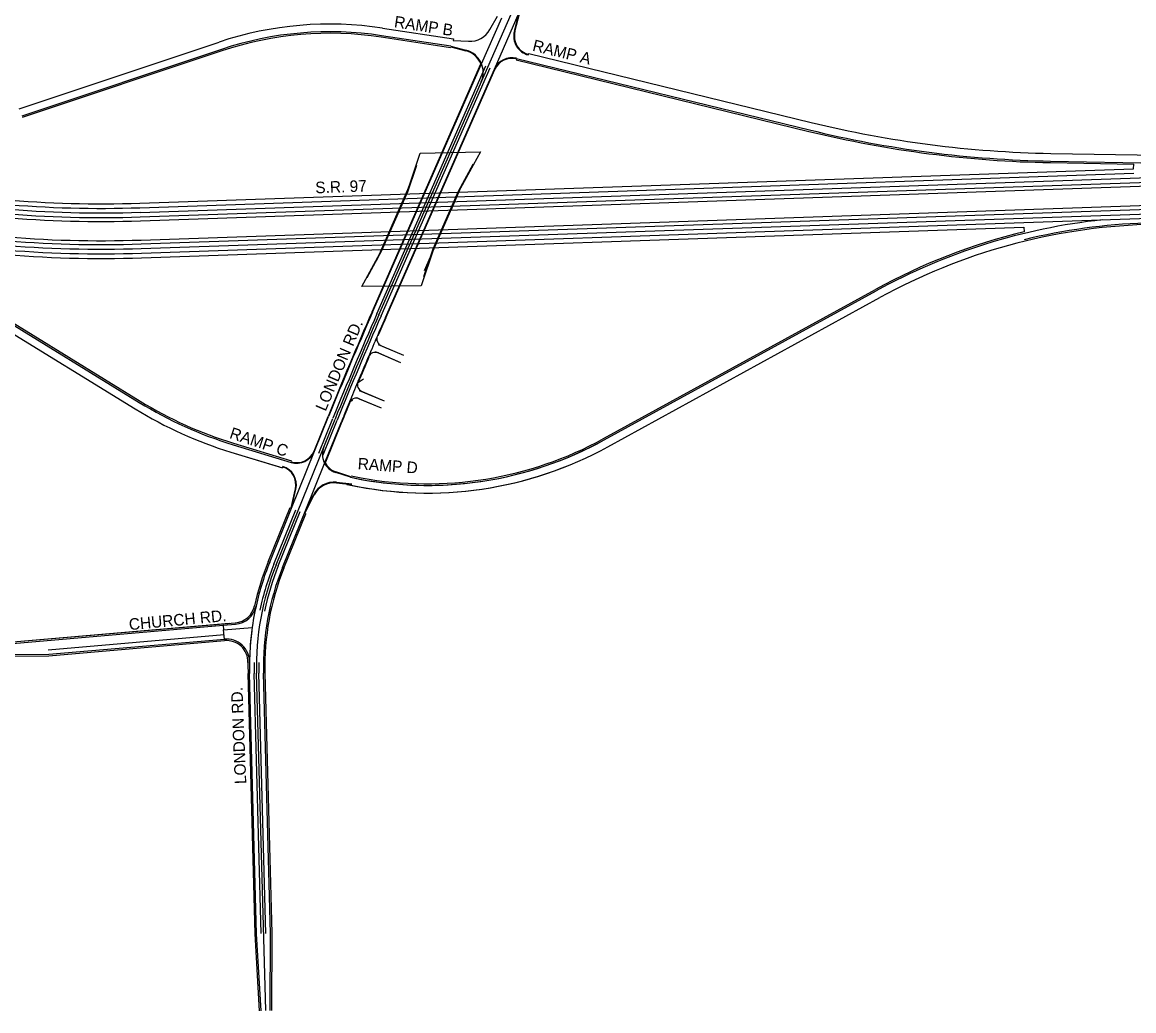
# Model space of a CAD drawing. Extents: x 2315515 to 2326910, y 758186 to 762794.
# Drawn here: x 2319970 to 2322857, y 758186 to 760752 of the extents above; entities that cross this region are included whole.
import ezdxf

# ---------------------------------------------------------------- set-up
doc = ezdxf.new("R2010")
doc.units = 0
for name, color, linetype in [('_CIVIL_CONSTRUCTION', 7, 'Continuous'), ('Bridge_Abutment', 7, 'Continuous'), ('Bridge_Bearing', 7, 'Continuous'), ('Bridge_Deck', 7, 'Continuous'), ('Clipping_Shape', 7, 'Continuous'), ('Default', 7, 'Continuous'), ('Draft_Corr_Final', 7, 'Continuous'), ('Draft_Corr_Range_Final', 7, 'Continuous'), ('Pavement Marking Yellow', 7, 'Continuous'), ('Road_Curb_Face', 7, 'Continuous'), ('TL_Base Extension Sub', 7, 'Continuous'), ('TL_End Condition Cut Tie', 7, 'Continuous'), ('TL_End Condition Ditch Out', 7, 'Continuous'), ('TL_End Condition Hinge', 7, 'Continuous'), ('TL_Pavement Centerline', 7, 'Continuous'), ('TL_Pavement Centerline Sub', 7, 'Continuous')]:
    doc.layers.add(name, color=color, linetype=linetype)

msp = doc.modelspace()

# ---------------------------------------------------------------- linework, layer by layer
at = {"layer": '_CIVIL_CONSTRUCTION'}
for p, q in [((2320276.8, 760236.3), (2324006.3, 760365.3)), ((2320278.5, 760186.3), (2324008.1, 760315.3))]:
    msp.add_line(p, q, dxfattribs=at)
for radius in [2941, 2991]:
    msp.add_arc((2320175.2, 763175.6), radius, 264.9144, 271.9805, dxfattribs=at)
at = {"layer": 'Bridge_Abutment'}
for p, q in [((2320970, 760308.5), (2320994, 760379.5)), ((2321103.2, 760313.3), (2321141.6, 760383.5)), ((2320904.4, 760159.2), (2320970, 760308.5)), ((2321037.2, 760163.2), (2321103.2, 760313.3)), ((2320866, 760089.1), (2320904.4, 760159.2)), ((2321013.2, 760092.1), (2321037.2, 760163.2))]:
    msp.add_line(p, q, dxfattribs=at)
at = {"layer": 'Bridge_Bearing'}
for p, q in [((2320994, 760379.5), (2320970, 760308.5)), ((2321141.6, 760383.5), (2321103.2, 760313.3)), ((2320904.4, 760159.2), (2320970, 760308.5)), ((2321037.2, 760163.2), (2321103.2, 760313.3)), ((2320866, 760089.1), (2320904.4, 760159.2)), ((2321013.2, 760092.1), (2321037.2, 760163.2))]:
    msp.add_line(p, q, dxfattribs=at)
at = {"layer": 'Bridge_Deck'}
for p, q in [((2320891.3, 760134.3), (2320977.7, 760331.1)), ((2320946.3, 760259.5), (2320966.8, 760306.2)), ((2321014.9, 760107.4), (2321107.7, 760318.6)), ((2321083.8, 760264.2), (2321104.3, 760311)), ((2320903.4, 760161.9), (2320924, 760208.7)), ((2321041, 760166.7), (2321061.5, 760213.4))]:
    msp.add_line(p, q, dxfattribs=at)
at = {"layer": 'Clipping_Shape'}
for p, q in [((2320969.1, 760308.8), (2320993.1, 760379.8)), ((2320903.6, 760159.7), (2320969.1, 760308.8)), ((2320865.1, 760089.5), (2320903.6, 760159.7))]:
    msp.add_line(p, q, dxfattribs=at)
msp.add_lwpolyline([(2320852.2, 760066.2), (2320904.3, 760161.4), (2320968.5, 760307.7), (2321003.8, 760411.9), (2321160.3, 760415.2), (2321103.4, 760311.5), (2321039.2, 760165.2), (2321006.2, 760067.6)], close=True, dxfattribs=at)
at = {"layer": 'Default'}
for p, q in [((2320896.6, 759992.2), (2321353.4, 761032.3)), ((2320896.6, 759992.2), (2321353.4, 761032.3)), ((2320896.6, 759992.2), (2321353.4, 761032.3)), ((2320840.7, 759815.8), (2320856, 759826.5)), ((2320820.4, 759766.7), (2320828.3, 759770.7)), ((2320629.4, 759343.1), (2320782.4, 759721.3)), ((2320629.4, 759343.1), (2320782.4, 759721.3)), ((2320629.4, 759343.1), (2320782.4, 759721.3)), ((2320602.3, 758186.1), (2320578.6, 759061.6)), ((2320602.3, 758186.1), (2320578.6, 759061.6)), ((2320602.3, 758186.1), (2320578.6, 759061.6))]:
    msp.add_line(p, q, dxfattribs=at)
for centre, radius, start, end in [((2330052.7, 755971.5), 10000, 156.2923, 157.9768), ((2330052.7, 755971.5), 10000, 156.2923, 157.9768), ((2330052.7, 755971.5), 10000, 156.2923, 157.9768), ((2321278.3, 759080.6), 700, 157.9768, 181.5499), ((2321278.3, 759080.6), 700, 157.9768, 181.5499), ((2321278.3, 759080.6), 700, 157.9768, 181.5499)]:
    msp.add_arc(centre, radius, start, end, dxfattribs=at)
at = {"layer": 'Draft_Corr_Final'}
for p, q in [((2321184.8, 760732.9), (2321204.5, 760767.9)), ((2321248.3, 760728.3), (2321261, 760777.3)), ((2321083.3, 760689.3), (2320902.9, 760716.9)), ((2321089.2, 760704.6), (2321129.4, 760702.5)), ((2320487.5, 760681.4), (2319968.8, 760508)), ((2321083.3, 760689.3), (2321122.2, 760679.3)), ((2321083.3, 760689.3), (2321122.2, 760679.3)), ((2320880.1, 759999.4), (2321163, 760643.5)), ((2320880.1, 759999.4), (2321163, 760643.5)), ((2321253.9, 760658.1), (2322014.4, 760472.4)), ((2321253.9, 760658.1), (2322014.4, 760472.4)), ((2320913.1, 759984.9), (2321196.2, 760629.7)), ((2320913.1, 759984.9), (2321196.2, 760629.7)), ((2322641, 760391.4), (2323391.1, 760378)), ((2322641, 760391.4), (2323391.1, 760378)), ((2321481.7, 759667.3), (2322187.7, 760054.5)), ((2321481.7, 759667.3), (2322187.7, 760054.5)), ((2319848.5, 760026.7), (2320274.1, 759765)), ((2320886.3, 759897), (2320952.1, 759868.7)), ((2320894.2, 759915.3), (2320960, 759887.1)), ((2320895.2, 759893.2), (2320952.1, 759868.7)), ((2320903, 759911.6), (2320960, 759887.1)), ((2320837.1, 759777.7), (2320902.4, 759750.7)), ((2320844.8, 759796.2), (2320910.1, 759769.1)), ((2320845.2, 759774.4), (2320902.4, 759750.7)), ((2320852.8, 759792.8), (2320910.1, 759769.1)), ((2320729.3, 759638), (2320765.7, 759728)), ((2320729.3, 759638), (2320765.7, 759728)), ((2320757.1, 759610.8), (2320799.1, 759714.5)), ((2320757.1, 759610.8), (2320799.1, 759714.5)), ((2320517.6, 759655.1), (2320668.3, 759608.9)), ((2320822.6, 759570.6), (2320784.3, 759582.8)), ((2320822.6, 759570.6), (2320784.3, 759582.8)), ((2320786.3, 759557.6), (2320826.3, 759553.5)), ((2320612.7, 759349.8), (2320680.2, 759516.6)), ((2320669.6, 759490.4), (2320680.9, 759539.8)), ((2320708.3, 759490.2), (2320727.1, 759525.8)), ((2320612.7, 759349.8), (2320669.6, 759490.4)), ((2320646.1, 759336.3), (2320712.8, 759501.1)), ((2320646.1, 759336.3), (2320708.3, 759490.2)), ((2319886.9, 759134), (2320492.1, 759186.2)), ((2320492.1, 759186.2), (2320523.9, 759189)), ((2320492.1, 759186.2), (2320523.9, 759189)), ((2320492.1, 759186.2), (2320493.2, 759174.3)), ((2320495.2, 759150.3), (2320493.2, 759174.3)), ((2320038.8, 759111), (2320495.2, 759150.3)), ((2320038.8, 759111), (2320495.2, 759150.3)), ((2319889, 759110.1), (2320038.8, 759111)), ((2320578.9, 758385.5), (2320560.6, 759061.2)), ((2320578.9, 758385.5), (2320560.6, 759061.2)), ((2320614.8, 758386.5), (2320596.6, 759062.1)), ((2320614.8, 758386.5), (2320596.6, 759062.1)), ((2320614.3, 758186.4), (2320614.8, 758386.5)), ((2320590.3, 758185.7), (2320578.9, 758385.5))]:
    msp.add_line(p, q, dxfattribs=at)
for centre, radius, start, end in [((2320768.6, 759840.1), 887, 81.2923, 108.4803), ((2321132.5, 760762.4), 60, 267.0029, 330.5817), ((2321296.6, 760715.6), 50, 165.3826, 256.2777), ((2321107.3, 760621.2), 60, 336.2923, 75.5817), ((2321107.3, 760621.2), 60, 21.8653, 75.5817), ((2321242, 760609.6), 50, 76.2777, 156.2923), ((2322691.8, 763246.9), 2856, 256.2777, 268.9805), ((2322691.8, 763246.9), 2856, 256.2777, 268.9805), ((2322940.8, 758681.5), 1566, 96.0766, 118.7415), ((2322940.8, 758681.5), 1566, 96.0766, 118.7415), ((2322940.8, 758681.5), 1550, 91.9805, 103.7445), ((2322940.8, 758681.5), 1550, 91.9805, 103.7445), ((2330052.7, 755971.5), 10018, 156.2923, 157.9768), ((2330052.7, 755971.5), 10018, 156.2923, 157.9768), ((2330052.7, 755971.5), 9982, 156.2923, 156.67031), ((2330052.7, 755971.5), 9982, 156.2923, 156.58701), ((2320910.9, 759929.9), 20, 156.587, 246.7596), ((2330052.7, 755971.5), 9982, 156.82209, 157.38068), ((2320887.3, 759874.8), 20, 66.7596, 156.9321), ((2330052.7, 755971.5), 9982, 156.93209, 157.32833), ((2320860.5, 759811.3), 20, 157.3283, 247.5009), ((2330052.7, 755971.5), 9982, 157.60715, 157.9768), ((2320837.5, 759755.9), 20, 67.5009, 157.6734), ((2320826.1, 760662.9), 1054, 238.4184, 252.9768), ((2330052.7, 755971.5), 9982, 157.67342, 157.9768), ((2321022, 760505.5), 956, 257.9603, 298.7415), ((2321022, 760505.5), 956, 258.6432, 298.7415), ((2320682.9, 759656.8), 50, 252.9768, 337.9768), ((2320799.6, 759630.4), 50, 157.9768, 252.2497), ((2320632.2, 759551), 50, 347.0671, 72.9768), ((2320799.6, 759630.4), 50, 200.9838, 252.2497), ((2320780.2, 759497.9), 60, 84.0948, 152.2662), ((2321278.3, 759080.6), 718, 157.9768, 168.1459), ((2321278.3, 759080.6), 718, 157.9768, 168.1459), ((2321278.3, 759080.6), 682, 157.9768, 181.5499), ((2321278.3, 759080.6), 682, 157.9768, 181.5499), ((2320518.7, 759248.7), 60, 274.9294, 347.5179), ((2320518.7, 759248.7), 60, 274.9294, 347.5179), ((2321278.3, 759080.6), 718, 172.8394, 181.5499), ((2320500.4, 759090.6), 60, 359.264, 94.9294), ((2321278.3, 759080.6), 718, 179.264, 181.5499)]:
    msp.add_arc(centre, radius, start, end, dxfattribs=at)
at = {"layer": 'Draft_Corr_Range_Final'}
for p, q in [((2320276.5, 760246.3), (2324006, 760375.3)), ((2320278.9, 760176.4), (2324008.4, 760305.3))]:
    msp.add_line(p, q, dxfattribs=at)
for radius in [2931, 3001]:
    msp.add_arc((2320175.2, 763175.6), radius, 264.9144, 271.9805, dxfattribs=at)
at = {"layer": 'Pavement Marking Yellow'}
for p, q in [((2320891.1, 759994.6), (2321174, 760638.7)), ((2320902.1, 759989.8), (2321185, 760633.9)), ((2320740.4, 759633.5), (2320776.8, 759723.5)), ((2320751.5, 759628.9), (2320787.9, 759719)), ((2320623.8, 759345.3), (2320680.7, 759485.9)), ((2320635, 759340.8), (2320691.8, 759481.4)), ((2320590.9, 758385.8), (2320572.6, 759061.5)), ((2320602.9, 758386.2), (2320584.6, 759061.8))]:
    msp.add_line(p, q, dxfattribs=at)
for centre, radius, start, end in [((2330052.7, 755971.5), 10006, 156.2923, 157.9768), ((2330052.7, 755971.5), 9994, 156.2923, 157.9768), ((2321278.3, 759080.6), 706, 157.9768, 168.1459), ((2321278.3, 759080.6), 694, 157.9768, 168.1459), ((2321278.3, 759080.6), 706, 179.264, 181.5499), ((2321278.3, 759080.6), 694, 179.264, 181.5499)]:
    msp.add_arc(centre, radius, start, end, dxfattribs=at)
at = {"layer": 'Road_Curb_Face'}
for p, q in [((2321249.7, 760727.9), (2321262.5, 760776.9)), ((2321249.7, 760727.9), (2321262.5, 760776.8)), ((2321082.9, 760687.8), (2321121.9, 760677.8)), ((2321083.1, 760687.8), (2321121.9, 760677.8)), ((2320878.8, 760000), (2321161.6, 760644.1)), ((2320878.8, 760000), (2321161.4, 760643.5)), ((2320914.5, 759984.3), (2321197.6, 760629.1)), ((2320727.9, 759638.6), (2320764.3, 759728.6)), ((2320727.9, 759638.6), (2320764.3, 759728.6)), ((2320757.2, 759606.9), (2320800.5, 759714)), ((2320758.5, 759610.3), (2320800.5, 759714)), ((2320823.1, 759572), (2320784.8, 759584.3)), ((2320823.1, 759572), (2320784.8, 759584.3)), ((2320786.2, 759556.1), (2320826.2, 759552)), ((2320668.1, 759490.8), (2320679.5, 759540.1)), ((2320668.1, 759490.5), (2320679.5, 759540.1)), ((2320709.7, 759489.5), (2320728.4, 759525.1)), ((2320704.4, 759476.4), (2320709.7, 759489.5))]:
    msp.add_line(p, q, dxfattribs=at)
for centre, radius, start, end in [((2321296.6, 760715.6), 48.5, 165.3826, 256.2777), ((2321296.6, 760715.6), 48.5, 165.3826, 256.2777), ((2321107.3, 760621.2), 58.5, 23.8009, 75.5817), ((2321107.3, 760621.2), 58.5, 22.4792, 75.5817), ((2321242, 760609.6), 48.5, 76.2777, 156.2923), ((2330052.7, 755971.5), 10019.5, 156.2923, 157.9768), ((2330052.7, 755971.5), 10019.5, 156.2923, 157.9768), ((2330052.7, 755971.5), 9980.5, 156.2923, 156.58701), ((2330052.7, 755971.5), 9980.5, 156.93209, 157.33984), ((2330052.7, 755971.5), 9980.5, 157.66192, 157.9768), ((2330052.7, 755971.5), 9980.5, 157.66192, 157.9768), ((2320682.9, 759656.8), 48.5, 252.9768, 337.9768), ((2320799.6, 759630.4), 48.5, 205.6722, 252.2497), ((2320799.6, 759630.4), 48.5, 209.0103, 252.2497), ((2320632.2, 759551), 48.5, 347.0671, 72.9768), ((2320632.2, 759551), 48.5, 347.0671, 72.9768), ((2320780.2, 759497.9), 58.5, 84.0948, 152.2662)]:
    msp.add_arc(centre, radius, start, end, dxfattribs=at)
at = {"layer": 'TL_Base Extension Sub'}
for p, q in [((2320276.1, 760258.3), (2324005.6, 760387.3)), ((2320279.3, 760164.4), (2324008.8, 760293.3)), ((2320037.8, 759122.9), (2320494.2, 759162.3))]:
    msp.add_line(p, q, dxfattribs=at)
for radius in [2919, 3013]:
    msp.add_arc((2320175.2, 763175.6), radius, 264.9144, 271.9805, dxfattribs=at)
at = {"layer": 'TL_End Condition Cut Tie'}
for p, q in [((2320905.9, 760736.7), (2321089.8, 760708.5)), ((2319962.4, 760527), (2320481.1, 760700.4)), ((2321082.7, 760685.3), (2320902.3, 760713)), ((2321089.8, 760708.5), (2321089.2, 760704.6)), ((2320488.7, 760677.6), (2319970, 760504.2)), ((2321284.8, 760667.1), (2321285.7, 760671)), ((2321285.7, 760671), (2322019.1, 760491.9)), ((2321253.9, 760658.1), (2321252.9, 760654.3)), ((2321252.9, 760654.3), (2322013.4, 760468.6)), ((2322641.4, 760411.4), (2323543.7, 760395.3)), ((2322641, 760387.4), (2322856.8, 760383.5)), ((2322856.6, 760371.6), (2322856.8, 760383.5)), ((2322571.6, 760219.6), (2322572, 760207.5)), ((2321479.8, 759670.8), (2322185.8, 760058)), ((2321491.3, 759649.8), (2322197.4, 760037)), ((2321491.3, 759649.8), (2322197.4, 760037)), ((2319838, 760009.6), (2320263.7, 759748)), ((2319838, 760009.6), (2320263.7, 759748)), ((2319850.6, 760030.1), (2320276.2, 759768.4)), ((2320518.7, 759658.9), (2320669.5, 759612.8)), ((2320511.7, 759636), (2320638.4, 759597.2)), ((2320511.7, 759636), (2320645.7, 759595)), ((2320646.8, 759598.8), (2320645.7, 759595)), ((2320824, 759574.2), (2320850.7, 759569.1)), ((2320813.2, 759552.1), (2320818.7, 759551)), ((2320821.1, 759554.5), (2320820.3, 759550.6)), ((2320609, 759351.3), (2320665.9, 759491.9)), ((2320649.8, 759334.8), (2320706.7, 759475.4)), ((2320703, 759476.9), (2320706.7, 759475.4)), ((2319886.6, 759138), (2320523.5, 759192.9)), ((2319886.6, 759138), (2320507.4, 759191.5)), ((2320039, 759107), (2320495.6, 759146.4)), ((2320039.2, 759107), (2320495.6, 759146.4)), ((2319888.5, 759106.1), (2320039, 759107)), ((2319889, 759106.1), (2320038.9, 759107)), ((2320574.9, 758385.4), (2320556.6, 759061)), ((2320574.9, 758385.3), (2320556.6, 759061)), ((2320618.8, 758386.6), (2320600.6, 759062.2)), ((2320618.3, 758186.4), (2320618.8, 758386.5)), ((2320618.3, 758186.4), (2320618.8, 758386.5)), ((2320586.3, 758185.5), (2320574.9, 758385.3)), ((2320586.3, 758185.5), (2320574.9, 758385.3))]:
    msp.add_line(p, q, dxfattribs=at)
for centre, radius, start, end in [((2320768.6, 759840.1), 907, 81.2923, 108.4803), ((2320768.6, 759840.1), 883, 81.2923, 108.4803), ((2322691.8, 763246.9), 2860, 256.2777, 268.9805), ((2322691.8, 763246.9), 2836, 256.2777, 268.9805), ((2322940.8, 758681.5), 1570, 103.585, 118.7415), ((2322940.8, 758681.5), 1546, 91.9805, 118.7415), ((2322940.8, 758681.5), 1546, 91.9805, 118.7415), ((2320826.1, 760662.9), 1074, 238.4184, 252.9768), ((2320826.1, 760662.9), 1074, 238.4184, 252.9768), ((2320826.1, 760662.9), 1050, 238.4184, 252.9768), ((2321022, 760505.5), 952, 259.6305, 298.7415), ((2321022, 760505.5), 976, 257.9768, 298.7415), ((2321022, 760505.5), 976, 258.0703, 298.7415), ((2321278.3, 759080.6), 722, 157.9768, 167.5179), ((2321278.3, 759080.6), 678, 157.9768, 181.5499), ((2320518.7, 759248.7), 56, 274.9294, 347.5179), ((2320518.7, 759248.7), 56, 274.9294, 347.5179), ((2320500.4, 759090.6), 56, 359.264, 94.9294), ((2321278.3, 759080.6), 722, 179.264, 181.5499), ((2321278.3, 759080.6), 722, 179.264, 181.5499)]:
    msp.add_arc(centre, radius, start, end, dxfattribs=at)
at = {"layer": 'TL_End Condition Ditch Out'}
for p, q in [((2321163, 760643.5), (2321215.5, 760763.1)), ((2321196.2, 760629.7), (2321261, 760777.3)), ((2322571.6, 760231.6), (2323686.3, 760270.2)), ((2320669.6, 759490.4), (2320729.3, 759638)), ((2320703, 759476.9), (2320757.1, 759610.8))]:
    msp.add_line(p, q, dxfattribs=at)
for centre, radius, start, end in [((2330052.7, 755971.5), 9982, 156.58701, 156.93209), ((2330052.7, 755971.5), 9982, 157.33984, 157.66192), ((2321278.3, 759080.6), 718, 167.5179, 179.264)]:
    msp.add_arc(centre, radius, start, end, dxfattribs=at)
at = {"layer": 'TL_End Condition Hinge'}
msp.add_line((2320493.2, 759174.3), (2320567.3, 759180.7), dxfattribs=at)
at = {"layer": 'TL_Pavement Centerline'}
for p, q in [((2320275.6, 760270.3), (2322857, 760359.6)), ((2320279.7, 760152.4), (2322571.6, 760231.6))]:
    msp.add_line(p, q, dxfattribs=at)
for radius in [2907, 3025]:
    msp.add_arc((2320175.2, 763175.6), radius, 264.9144, 271.9805, dxfattribs=at)
at = {"layer": 'TL_Pavement Centerline Sub'}
for p, q in [((2320275.2, 760282.3), (2322856.6, 760371.6)), ((2320280.1, 760140.4), (2322571.6, 760219.6))]:
    msp.add_line(p, q, dxfattribs=at)
for radius in [2895, 3037]:
    msp.add_arc((2320175.2, 763175.6), radius, 264.9144, 271.9805, dxfattribs=at)

# ---------------------------------------------------------------- texts
at = {"layer": 'Default'}
for s, rotation, p in [('RAMP B', 351.3639, (2320934.5, 760739)), ('RAMP A', 346.2856, (2321293.4, 760678.2)), ('S.R. 97', 2.1074, (2320731.7, 760307.5)), ('LONDON RD.', 67.0887, (2320757.9, 759740)), ('RAMP C', 341.6007, (2320506.3, 759672.7)), ('RAMP D', 355.8776, (2320840.6, 759591.4)), ('CHURCH RD.', 5.3529, (2320248.5, 759173.5)), ('LONDON RD.', 92.2882, (2320552.1, 758774.7))]:
    msp.add_text(s, height=30, rotation=rotation, dxfattribs=at).set_placement(p)

doc.saveas('drawing.dxf')
